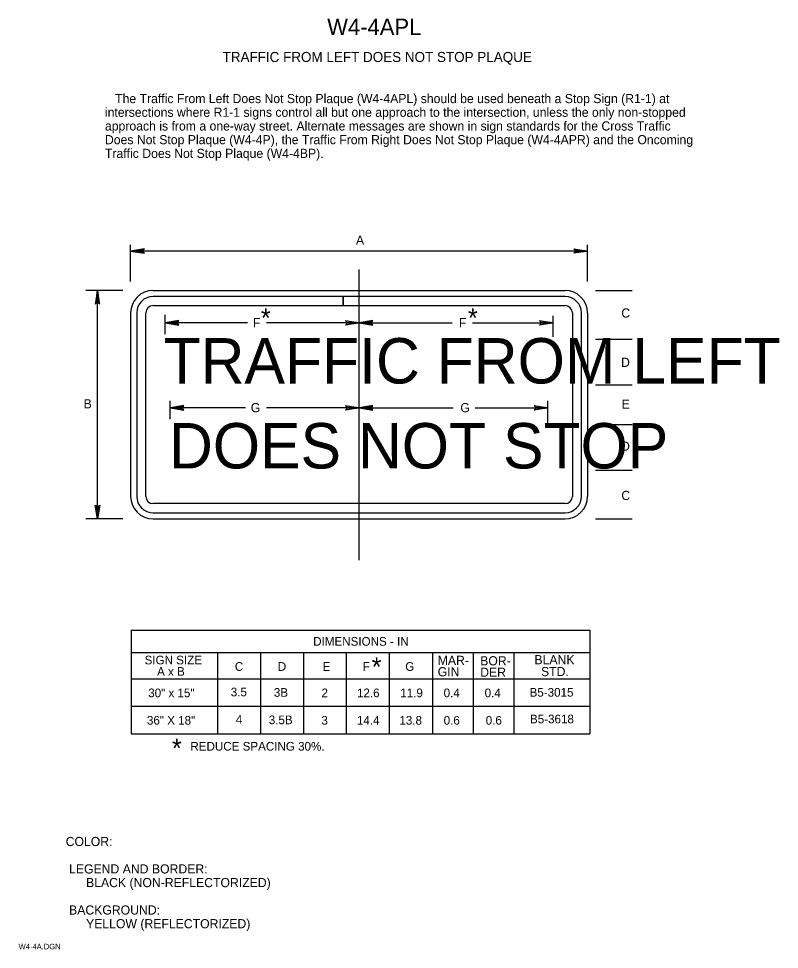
# Model space of a CAD drawing. Extents: x 0.013 to 0.221, y 0.004 to 0.259.
import ezdxf

# ---------------------------------------------------------------- set-up
doc = ezdxf.new("R2010")
doc.units = 0
for name, color, linetype in [('1', 7, 'Continuous'), ('2', 7, 'Continuous'), ('3', 7, 'Continuous')]:
    doc.layers.add(name, color=color, linetype=linetype)

# ---------------------------------------------------------------- blocks, each defined once
blk = doc.blocks.new('RARROW')
at = {"layer": '3'}
for p, q in [((-2.156, 0.285), (-2.2665, 0.384625)), ((-2.2665, 0.384625), (0, 0)), ((0, 0), (-2.2665, -0.379125)), ((-2.156, 0.285), (-2.075625, 0.12075)), ((0, 0), (-2.156, 0.285)), ((-2.14975, -0.2705), (0, 0)), ((-2.075625, 0.12075), (0, 0)), ((0, 0), (-2.074, -0.108)), ((-2.2665, -0.379125), (-2.14975, -0.2705)), ((-2.074, -0.108), (-2.14975, -0.2705))]:
    blk.add_line(p, q, dxfattribs=at)

msp = doc.modelspace()

# ---------------------------------------------------------------- linework, layer by layer
at = {"layer": '1'}
for p, q in [((0.10565, 0.11086), (0.10565, 0.19039)), ((0.0341, 0.12213), (0.0341, 0.18463)), ((0.10127, 0.18297), (0.04931, 0.18297)), ((0.10127, 0.18047), (0.10127, 0.18297)), ((0.16198, 0.18297), (0.10127, 0.18297)), ((0.10127, 0.18297), (0.10127, 0.18047)), ((0.04481, 0.17847), (0.04481, 0.1283)), ((0.04731, 0.1283), (0.04731, 0.17847)), ((0.04931, 0.18047), (0.10127, 0.18047)), ((0.10127, 0.18047), (0.16198, 0.18047)), ((0.16398, 0.17847), (0.16398, 0.1283)), ((0.16648, 0.1283), (0.16648, 0.17847)), ((0.05256, 0.17266), (0.05256, 0.17793)), ((0.10565, 0.17326), (0.10565, 0.17793)), ((0.15873, 0.17194), (0.15873, 0.17769)), ((0.05398, 0.14943), (0.05398, 0.15446)), ((0.10565, 0.15098), (0.10565, 0.1541)), ((0.15731, 0.14823), (0.15731, 0.15446)), ((0.16198, 0.1263), (0.04931, 0.1263)), ((0.04931, 0.1238), (0.16198, 0.1238))]:
    msp.add_line(p, q, dxfattribs=at)
for centre, radius, start, end in [((0.04931, 0.17847), 0.00617, 90, 180), ((0.16198, 0.17847), 0.00617, 360, 90), ((0.04931, 0.17847), 0.0045, 90, 180), ((0.16198, 0.17847), 0.0045, 0, 90), ((0.04931, 0.17847), 0.002, 90, 180), ((0.16198, 0.17847), 0.002, 0, 90), ((0.04931, 0.1283), 0.00617, 180, 270), ((0.04931, 0.1283), 0.0045, 180, 270), ((0.04931, 0.1283), 0.002, 180, 270), ((0.16198, 0.1283), 0.00617, 270, 0), ((0.16198, 0.1283), 0.0045, 270, 0), ((0.16198, 0.1283), 0.002, 270, 0)]:
    msp.add_arc(centre, radius, start, end, dxfattribs=at)
at = {"layer": '3'}
for p, q in [((0.04315, 0.18704), (0.04315, 0.1971)), ((0.16815, 0.18704), (0.16815, 0.1971)), ((0.16815, 0.19541), (0.04315, 0.19541)), ((0.04098, 0.18463), (0.03092, 0.18463)), ((0.04931, 0.18463), (0.16198, 0.18463)), ((0.17031, 0.18463), (0.18037, 0.18463)), ((0.04315, 0.17847), (0.04315, 0.1283)), ((0.16815, 0.17847), (0.16815, 0.1283)), ((0.07509, 0.17577), (0.05256, 0.17577)), ((0.10565, 0.17577), (0.08036, 0.17577)), ((0.10565, 0.17577), (0.13114, 0.17577)), ((0.13665, 0.17577), (0.15873, 0.17577)), ((0.17031, 0.1713), (0.18037, 0.1713)), ((0.17031, 0.1588), (0.18037, 0.1588)), ((0.07461, 0.15254), (0.05398, 0.15254)), ((0.10565, 0.15254), (0.08036, 0.15254)), ((0.10565, 0.15254), (0.13138, 0.15254)), ((0.13737, 0.15254), (0.15731, 0.15254)), ((0.17031, 0.14796), (0.18037, 0.14796)), ((0.17031, 0.13546), (0.18037, 0.13546)), ((0.04098, 0.12213), (0.03092, 0.12213)), ((0.04931, 0.12213), (0.16198, 0.12213)), ((0.17031, 0.12213), (0.18037, 0.12213)), ((0.04333, 0.09173), (0.16877, 0.09173)), ((0.04333, 0.09168), (0.04333, 0.06336)), ((0.16877, 0.09173), (0.16877, 0.06336)), ((0.16877, 0.08548), (0.04333, 0.08548)), ((0.0669, 0.08548), (0.0669, 0.06336)), ((0.07865, 0.08543), (0.07865, 0.06336)), ((0.0904, 0.08543), (0.0904, 0.06336)), ((0.10215, 0.08543), (0.10215, 0.06336)), ((0.1139, 0.08543), (0.1139, 0.06336)), ((0.12571, 0.08548), (0.12571, 0.06336)), ((0.13684, 0.08548), (0.13684, 0.06336)), ((0.14796, 0.08548), (0.14796, 0.06336)), ((0.04333, 0.07836), (0.16877, 0.07836)), ((0.04333, 0.07086), (0.16877, 0.07086)), ((0.04333, 0.06336), (0.16877, 0.06336))]:
    msp.add_line(p, q, dxfattribs=at)

# ---------------------------------------------------------------- block references
at = {"layer": '3', "xscale": 0.0016545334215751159}
for p, yscale, rotation in [((0.04315, 0.19541), -0.0016366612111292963, -180), ((0.0341, 0.18463), -0.0016366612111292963, 90), ((0.05256, 0.17577), -0.0016366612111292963, -180), ((0.10565, 0.17577), -0.0016366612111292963, -180), ((0.05398, 0.15254), -0.0016366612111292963, -180), ((0.10565, 0.15254), -0.0016366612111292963, -180), ((0.0341, 0.12213), 0.0016366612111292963, -90)]:
    msp.add_blockref('RARROW', p, dxfattribs=dict(at, yscale=yscale, rotation=rotation))
at = {"layer": '3', "xscale": 0.0016545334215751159, "yscale": 0.0016366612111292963}
for p in [(0.16815, 0.19541), (0.10565, 0.17577), (0.15873, 0.17577), (0.10565, 0.15254), (0.15731, 0.15254)]:
    msp.add_blockref('RARROW', p, dxfattribs=at)

# ---------------------------------------------------------------- texts
at = {"layer": '1'}
for s, height, p in [('W4-4APL', 0.0045, (0.09692, 0.2545)), ('TRAFFIC FROM LEFT DOES NOT STOP PLAQUE', 0.0027503, (0.06831, 0.24713)), ('COLOR:', 0.0025, (0.02538, 0.03262)), (' LEGEND AND BORDER:', 0.0024998, (0.02538, 0.02512)), ('      BLACK (NON-REFLECTORIZED)', 0.0024998, (0.02538, 0.02138)), (' BACKGROUND:', 0.0024998, (0.02538, 0.01388)), ('      YELLOW (REFLECTORIZED)', 0.0024998, (0.02538, 0.01013)), ('W4-4A.DGN', 0.0015, (0.0125, 0.00438))]:
    msp.add_text(s, height=height, dxfattribs=at).set_placement(p)
at = {"layer": '2'}
for s, height, p in [('   The Traffic From Left Does Not Stop Plaque (W4-4APL) should be used beneath a Stop Sign (R1-1) at ', 0.00249975, (0.03612, 0.23588)), ('intersections where R1-1 signs control all but one approach to the intersection, unless the only non-stopped ', 0.00249975, (0.03612, 0.23213)), ('approach is from a one-way street. Alternate messages are shown in sign standards for the Cross Traffic ', 0.00249975, (0.03612, 0.22838)), ('Does Not Stop Plaque (W4-4P), the Traffic From Right Does Not Stop Plaque (W4-4APR) and the Oncoming ', 0.00249975, (0.03612, 0.22463)), ('Traffic Does Not Stop Plaque (W4-4BP).', 0.0024998, (0.03612, 0.22088))]:
    msp.add_text(s, height=height, dxfattribs=at).set_placement(p)
at = {"layer": '3'}
for s, height, p in [('A', 0.0025, (0.10479, 0.19716)), ('*', 0.00518, (0.07877, 0.17455)), ('C', 0.0025, (0.17738, 0.1772)), ('F', 0.0025, (0.13297, 0.17456)), ('TRAFFIC FROM LEFT', 0.01242, (0.05215, 0.15917)), ('B', 0.0025, (0.03028, 0.15237)), ('G', 0.0025, (0.13334, 0.15132)), ('DOES NOT STOP', 0.01242, (0.05365, 0.13593)), ('DIMENSIONS - IN', 0.0023752, (0.09309, 0.08743)), ('SIGN SIZE', 0.002375, (0.04697, 0.08233)), ('MAR-', 0.0025, (0.12715, 0.08218)), ('BOR-', 0.0025, (0.13877, 0.08206)), ('BLANK', 0.0025, (0.15361, 0.08236)), ('A x B', 0.002375, (0.05038, 0.07921)), ('C', 0.00238, (0.07165, 0.08056)), ('D', 0.00238, (0.0834, 0.08056)), ('E', 0.00238, (0.09565, 0.08056)), ('F', 0.00238, (0.10665, 0.08056)), ('G', 0.00238, (0.11827, 0.08056)), ('GIN', 0.0025, (0.12715, 0.07906)), ('STD.', 0.0025, (0.15541, 0.07911)), ('DER', 0.0025, (0.13877, 0.07893)), ('30" x 15"', 0.002375, (0.04796, 0.07334)), ('3.5', 0.002375, (0.07053, 0.07358)), ('3B', 0.002375, (0.08233, 0.07346)), ('2', 0.00238, (0.09536, 0.07333)), ('12.6', 0.002375, (0.10506, 0.07334)), ('11.9', 0.002375, (0.11691, 0.07334)), ('0.4', 0.002375, (0.12877, 0.07334)), ('B5-3015', 0.002375, (0.15228, 0.07349)), ('36" X 18"', 0.002375, (0.04761, 0.06584)), ('4', 0.00238, (0.07192, 0.06608)), ('3.5B', 0.002375, (0.08093, 0.06596)), ('3', 0.00238, (0.09534, 0.06583)), ('14.4', 0.002375, (0.10505, 0.06584)), ('13.8', 0.002375, (0.11667, 0.06584)), ('0.6', 0.002375, (0.12878, 0.06584)), ('B5-3618', 0.002375, (0.15239, 0.06619)), ('REDUCE SPACING 30%.', 0.0023752, (0.05949, 0.05873))]:
    msp.add_text(s, height=height, dxfattribs=at).set_placement(p)
for s, height, p in [('*', 0.00518, (0.13542, 0.17455)), ('F', 0.0025, (0.07661, 0.17456)), ('D', 0.0025, (0.1773, 0.16372)), ('G', 0.0025, (0.07602, 0.15132)), ('E', 0.0025, (0.17744, 0.15228)), ('D', 0.0025, (0.1773, 0.14078)), ('C', 0.0025, (0.17738, 0.1273)), ('*', 0.00518, (0.10909, 0.0791)), ('0.4', 0.002375, (0.13999, 0.07334)), ('0.6', 0.002375, (0.14028, 0.06584)), ('*', 0.00518, (0.05444, 0.05682))]:
    msp.add_text(s, height=height, rotation=360, dxfattribs=at).set_placement(p)

doc.saveas('drawing.dxf')
